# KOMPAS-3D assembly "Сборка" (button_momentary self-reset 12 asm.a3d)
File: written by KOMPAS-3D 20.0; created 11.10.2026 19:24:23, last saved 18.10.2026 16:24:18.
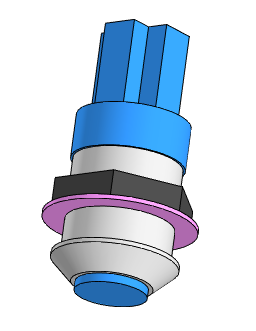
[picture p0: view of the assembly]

Document properties: Полное имя файла: D:\myProjects\Progect_esp32\box_compas\переключатели и кнопки\button_momentary self-reset 12 asm.a3d

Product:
- Part/product: Сборка
    Масса: 0.0237077
  - Component [detail]: Деталь  | Масса: 0.0186527; source file: button_momentary self-reset 12.m3d
  - Component [detail]: Деталь  | Масса: 0.00505493; source file: button_momentary self-reset 12 up.m3d

Referenced files in D:\myProjects\Progect_esp32\box_compas\переключатели и кнопки\: button_momentary self-reset 12.m3d, button_momentary self-reset 12 up.m3d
